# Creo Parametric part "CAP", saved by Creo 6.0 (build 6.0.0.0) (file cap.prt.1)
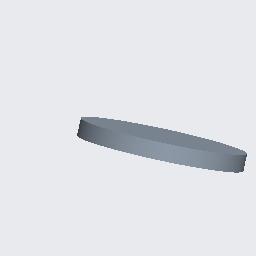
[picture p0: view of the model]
Units: millimeter Newton Second (mmNs); MM, TONNE, SECS

Created from: MMNS_PART_SOLID.PRT

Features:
  1. datum plane "RIGHT"
  2. datum plane "TOP"
  3. datum plane "FRONT"
  4. coordinate system
  5. sketch "Sketch 1"
  6. extrusion "Extrude 1"

Surfaces: 2 plane, 1 cylinder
